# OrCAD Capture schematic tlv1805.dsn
size A
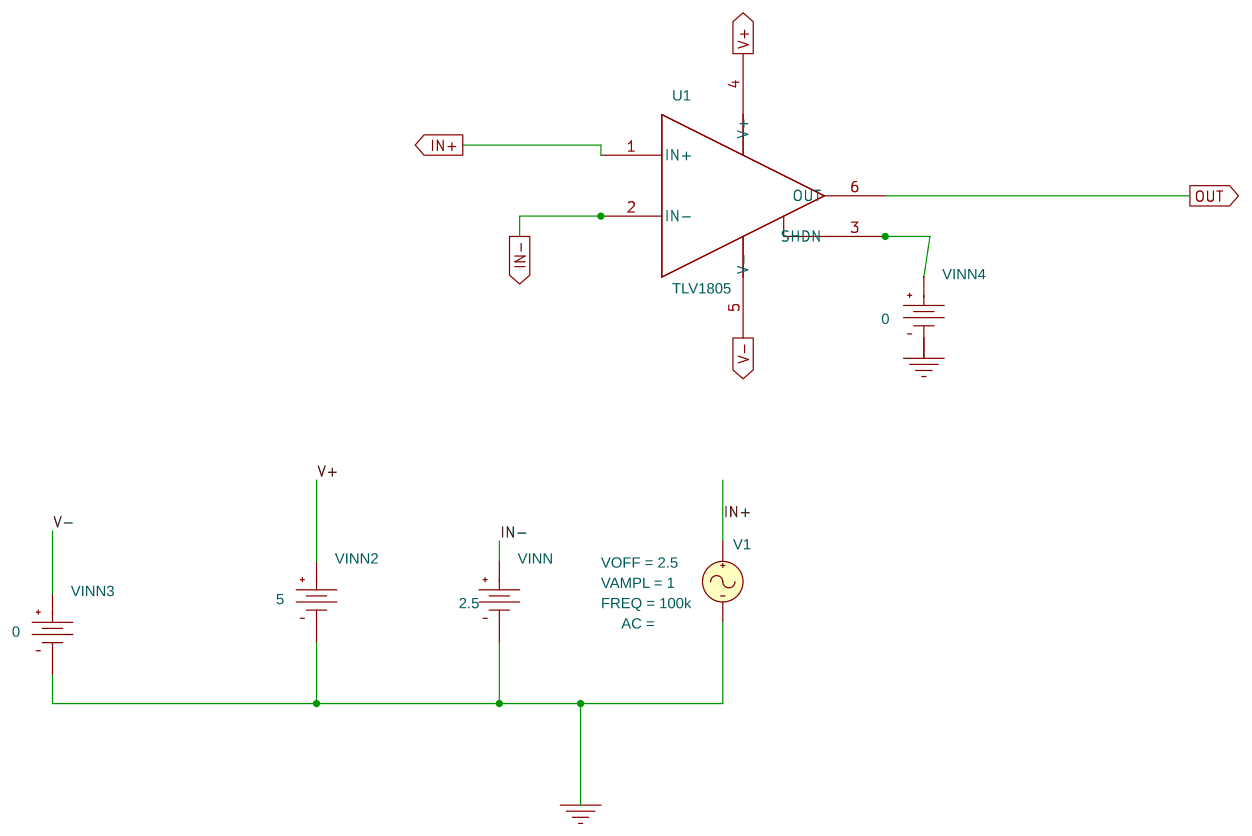
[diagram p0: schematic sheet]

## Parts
U1  TLV1805
V1  VSIN
VINN  VDC
VINN2  VDC
VINN3  VDC
VINN4  VDC

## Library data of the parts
U1 = TLV1805
V1 = VSIN: FREQ: 100k; VAMPL: 1; VOFF: 2.5
VINN = VDC: DC: 2.5
VINN2 = VDC: DC: 5
VINN3 VINN4 = VDC: DC: 0

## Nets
0: V1.2(-) VINN.1(-) VINN2.1(-) VINN3.1(-) VINN4.1(-)
IN+: U1.1(IN+) V1.1(+)
IN-: U1.2(IN-) VINN.0(+)
OUT: U1.6(OUT)
V+: U1.4(V+) VINN2.0(+)
V-: U1.5(V-) VINN3.0(+)
N850340: U1.3(SHDN) VINN4.0(+)
